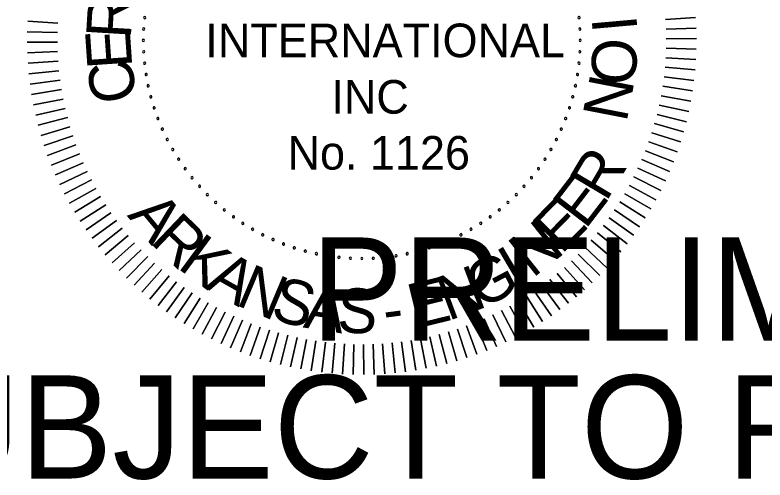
# Model space of a CAD drawing. Extents: x -0.54 to 1.64, y 0 to 0.92.
# Drawn here: x 1.1157 to 1.21, y 0.0548 to 0.1133 of the extents above; entities that cross this region are included whole.
import ezdxf

# ---------------------------------------------------------------- set-up
doc = ezdxf.new("R2010")
doc.units = 0
doc.layers.add('SHET_Stamp-Prelim', color=7, linetype='Continuous')
doc.layers.add('STAMP_COA', color=7, linetype='Continuous')

msp = doc.modelspace()

# ---------------------------------------------------------------- linework, layer by layer
at = {"layer": 'STAMP_COA'}
for points in [[(1.1211, 0.112275), (1.117313, 0.112493)], [(1.117313, 0.112493), (1.1211, 0.112275)], [(1.201265, 0.11296), (1.197481, 0.112701)], [(1.197481, 0.112701), (1.201265, 0.11296)], [(1.201335, 0.111641), (1.197545, 0.111501)], [(1.197545, 0.111501), (1.201335, 0.111641)], [(1.12105, 0.111074), (1.117258, 0.111172)], [(1.117258, 0.111172), (1.12105, 0.111074)], [(1.201363, 0.11032), (1.19757, 0.110299)], [(1.19757, 0.110299), (1.201363, 0.11032)], [(1.121038, 0.109872), (1.117245, 0.109851)], [(1.117245, 0.109851), (1.121038, 0.109872)], [(1.121064, 0.10867), (1.117273, 0.10853)], [(1.117273, 0.10853), (1.121064, 0.10867)], [(1.20135, 0.108999), (1.197558, 0.109097)], [(1.197558, 0.109097), (1.20135, 0.108999)], [(1.201295, 0.107679), (1.197508, 0.107896)], [(1.197508, 0.107896), (1.201295, 0.107679)], [(1.121127, 0.10747), (1.117343, 0.107211)], [(1.117343, 0.107211), (1.121127, 0.10747)], [(1.201199, 0.106361), (1.19742, 0.106697)], [(1.19742, 0.106697), (1.201199, 0.106361)], [(1.121228, 0.106272), (1.117454, 0.105894)], [(1.117454, 0.105894), (1.121228, 0.106272)], [(1.121366, 0.105078), (1.117606, 0.104582)], [(1.117606, 0.104582), (1.121366, 0.105078)], [(1.201061, 0.105047), (1.197295, 0.105501)], [(1.197295, 0.105501), (1.201061, 0.105047)], [(1.121542, 0.103889), (1.117799, 0.103275)], [(1.117799, 0.103275), (1.121542, 0.103889)], [(1.200882, 0.103738), (1.197132, 0.10431)], [(1.197132, 0.10431), (1.200882, 0.103738)], [(1.200662, 0.102435), (1.196932, 0.103125)], [(1.196932, 0.103125), (1.200662, 0.102435)], [(1.121756, 0.102706), (1.118034, 0.101974)], [(1.118034, 0.101974), (1.121756, 0.102706)], [(1.200401, 0.101139), (1.196695, 0.101946)], [(1.196695, 0.101946), (1.200401, 0.101139)], [(1.122006, 0.10153), (1.118309, 0.100682)], [(1.118309, 0.100682), (1.122006, 0.10153)], [(1.122293, 0.100363), (1.118625, 0.099399)], [(1.118625, 0.099399), (1.122293, 0.100363)], [(1.2001, 0.099853), (1.196421, 0.100776)], [(1.196421, 0.100776), (1.2001, 0.099853)], [(1.122617, 0.099205), (1.11898, 0.098126)], [(1.11898, 0.098126), (1.122617, 0.099205)], [(1.199759, 0.098577), (1.19611, 0.099614)], [(1.19611, 0.099614), (1.199759, 0.098577)], [(1.122977, 0.098058), (1.119376, 0.096866)], [(1.119376, 0.096866), (1.122977, 0.098058)], [(1.199377, 0.097312), (1.195763, 0.098464)], [(1.195763, 0.098464), (1.199377, 0.097312)], [(1.198956, 0.096059), (1.19538, 0.097324)], [(1.19538, 0.097324), (1.198956, 0.096059)], [(1.123372, 0.096923), (1.119811, 0.095618)], [(1.119811, 0.095618), (1.123372, 0.096923)], [(1.198496, 0.094821), (1.194961, 0.096197)], [(1.194961, 0.096197), (1.198496, 0.094821)], [(1.123804, 0.095801), (1.120285, 0.094385)], [(1.120285, 0.094385), (1.123804, 0.095801)], [(1.12427, 0.094693), (1.120797, 0.093167)], [(1.120797, 0.093167), (1.12427, 0.094693)], [(1.197997, 0.093597), (1.194508, 0.095084)], [(1.194508, 0.095084), (1.197997, 0.093597)], [(1.124771, 0.0936), (1.121348, 0.091966)], [(1.121348, 0.091966), (1.124771, 0.0936)], [(1.19746, 0.09239), (1.194019, 0.093986)], [(1.194019, 0.093986), (1.19746, 0.09239)], [(1.125306, 0.092523), (1.121936, 0.090782)], [(1.121936, 0.090782), (1.125306, 0.092523)], [(1.196885, 0.0912), (1.193496, 0.092903)], [(1.193496, 0.092903), (1.196885, 0.0912)], [(1.125874, 0.091464), (1.12256, 0.089618)], [(1.12256, 0.089618), (1.125874, 0.091464)], [(1.196274, 0.090029), (1.19294, 0.091838)], [(1.19294, 0.091838), (1.196274, 0.090029)], [(1.195625, 0.088877), (1.19235, 0.09079)], [(1.19235, 0.09079), (1.195625, 0.088877)], [(1.126475, 0.090423), (1.123221, 0.088474)], [(1.123221, 0.088474), (1.126475, 0.090423)], [(1.194941, 0.087747), (1.191727, 0.089762)], [(1.191727, 0.089762), (1.194941, 0.087747)], [(1.127109, 0.089402), (1.123918, 0.087351)], [(1.123918, 0.087351), (1.127109, 0.089402)], [(1.194222, 0.086639), (1.191073, 0.088753)], [(1.191073, 0.088753), (1.194222, 0.086639)], [(1.127775, 0.0884), (1.12465, 0.086251)], [(1.12465, 0.086251), (1.127775, 0.0884)], [(1.193468, 0.085553), (1.190387, 0.087766)], [(1.190387, 0.087766), (1.193468, 0.085553)], [(1.128471, 0.087421), (1.125415, 0.085174)], [(1.125415, 0.085174), (1.128471, 0.087421)], [(1.192681, 0.084492), (1.189671, 0.086801)], [(1.189671, 0.086801), (1.192681, 0.084492)], [(1.129199, 0.086464), (1.126214, 0.084122)], [(1.126214, 0.084122), (1.129199, 0.086464)], [(1.191861, 0.083457), (1.188925, 0.085858)], [(1.188925, 0.085858), (1.191861, 0.083457)], [(1.129955, 0.08553), (1.127046, 0.083095)], [(1.127046, 0.083095), (1.129955, 0.08553)], [(1.191008, 0.082447), (1.188149, 0.08494)], [(1.188149, 0.08494), (1.191008, 0.082447)], [(1.130741, 0.08462), (1.12791, 0.082096)], [(1.12791, 0.082096), (1.130741, 0.08462)], [(1.190124, 0.081465), (1.187345, 0.084046)], [(1.187345, 0.084046), (1.190124, 0.081465)], [(1.131555, 0.083735), (1.128805, 0.081123)], [(1.128805, 0.081123), (1.131555, 0.083735)], [(1.18921, 0.080511), (1.186513, 0.083178)], [(1.186513, 0.083178), (1.18921, 0.080511)], [(1.132397, 0.082877), (1.129729, 0.08018)], [(1.129729, 0.08018), (1.132397, 0.082877)], [(1.133265, 0.082045), (1.130683, 0.079265)], [(1.130683, 0.079265), (1.133265, 0.082045)], [(1.188266, 0.079586), (1.185654, 0.082337)], [(1.185654, 0.082337), (1.188266, 0.079586)], [(1.131666, 0.078382), (1.134158, 0.081241)], [(1.134158, 0.081241), (1.131666, 0.078382)], [(1.187294, 0.078692), (1.18477, 0.081523)], [(1.18477, 0.081523), (1.187294, 0.078692)], [(1.132675, 0.077529), (1.135077, 0.080465)], [(1.135077, 0.080465), (1.132675, 0.077529)], [(1.186294, 0.077828), (1.18386, 0.080737)], [(1.18386, 0.080737), (1.186294, 0.077828)], [(1.133711, 0.076709), (1.136019, 0.079719)], [(1.136019, 0.079719), (1.133711, 0.076709)], [(1.184215, 0.076197), (1.181969, 0.079253)], [(1.181969, 0.079253), (1.184215, 0.076197)], [(1.185268, 0.076996), (1.182926, 0.07998)], [(1.182926, 0.07998), (1.185268, 0.076996)], [(1.134772, 0.075921), (1.136984, 0.079002)], [(1.136984, 0.079002), (1.134772, 0.075921)], [(1.135857, 0.075168), (1.137972, 0.078317)], [(1.137972, 0.078317), (1.135857, 0.075168)], [(1.183139, 0.075431), (1.180989, 0.078556)], [(1.180989, 0.078556), (1.183139, 0.075431)], [(1.136966, 0.074448), (1.13898, 0.077662)], [(1.13898, 0.077662), (1.136966, 0.074448)], [(1.182038, 0.074699), (1.179988, 0.077891)], [(1.179988, 0.077891), (1.182038, 0.074699)], [(1.138096, 0.073764), (1.140009, 0.07704)], [(1.140009, 0.07704), (1.138096, 0.073764)], [(1.139247, 0.073116), (1.141056, 0.07645)], [(1.141056, 0.07645), (1.139247, 0.073116)], [(1.179772, 0.073342), (1.177926, 0.076655)], [(1.177926, 0.076655), (1.179772, 0.073342)], [(1.180916, 0.074003), (1.178967, 0.077257)], [(1.178967, 0.077257), (1.180916, 0.074003)], [(1.140418, 0.072504), (1.142122, 0.075893)], [(1.142122, 0.075893), (1.140418, 0.072504)], [(1.177424, 0.072129), (1.17579, 0.075552)], [(1.17579, 0.075552), (1.177424, 0.072129)], [(1.178607, 0.072717), (1.176866, 0.076087)], [(1.176866, 0.076087), (1.178607, 0.072717)], [(1.141608, 0.07193), (1.143204, 0.075371)], [(1.143204, 0.075371), (1.141608, 0.07193)], [(1.142815, 0.071393), (1.144302, 0.074882)], [(1.144302, 0.074882), (1.142815, 0.071393)], [(1.175005, 0.071066), (1.173589, 0.074585)], [(1.173589, 0.074585), (1.175005, 0.071066)], [(1.176223, 0.071579), (1.174697, 0.075051)], [(1.174697, 0.075051), (1.176223, 0.071579)], [(1.144039, 0.070894), (1.145416, 0.074428)], [(1.145416, 0.074428), (1.144039, 0.070894)], [(1.145278, 0.070434), (1.146543, 0.07401)], [(1.146543, 0.07401), (1.145278, 0.070434)], [(1.14653, 0.070013), (1.147682, 0.073626)], [(1.147682, 0.073626), (1.14653, 0.070013)], [(1.172524, 0.070157), (1.171332, 0.073758)], [(1.171332, 0.073758), (1.172524, 0.070157)], [(1.173772, 0.070592), (1.172467, 0.074154)], [(1.172467, 0.074154), (1.173772, 0.070592)], [(1.147795, 0.069631), (1.148833, 0.073279)], [(1.148833, 0.073279), (1.147795, 0.069631)], [(1.149071, 0.06929), (1.149994, 0.072969)], [(1.149994, 0.072969), (1.149071, 0.06929)], [(1.150358, 0.068988), (1.151165, 0.072695)], [(1.151165, 0.072695), (1.150358, 0.068988)], [(1.168708, 0.06909), (1.16786, 0.072788)], [(1.16786, 0.072788), (1.168708, 0.06909)], [(1.169991, 0.069406), (1.169027, 0.073075)], [(1.169027, 0.073075), (1.169991, 0.069406)], [(1.171263, 0.069762), (1.170185, 0.073398)], [(1.170185, 0.073398), (1.171263, 0.069762)], [(1.151653, 0.068728), (1.152343, 0.072457)], [(1.152343, 0.072457), (1.151653, 0.068728)], [(1.152956, 0.068508), (1.153529, 0.072257)], [(1.153529, 0.072257), (1.152956, 0.068508)], [(1.154265, 0.068329), (1.15472, 0.072094)], [(1.15472, 0.072094), (1.154265, 0.068329)], [(1.155579, 0.068191), (1.155915, 0.071969)], [(1.155915, 0.071969), (1.155579, 0.068191)], [(1.156897, 0.068095), (1.157114, 0.071882)], [(1.157114, 0.071882), (1.156897, 0.068095)], [(1.158217, 0.06804), (1.158315, 0.071832)], [(1.158315, 0.071832), (1.158217, 0.06804)], [(1.159538, 0.068026), (1.159517, 0.071819)], [(1.159517, 0.071819), (1.159538, 0.068026)], [(1.160859, 0.068055), (1.160719, 0.071845)], [(1.160719, 0.071845), (1.160859, 0.068055)], [(1.162179, 0.068124), (1.16192, 0.071908)], [(1.16192, 0.071908), (1.162179, 0.068124)], [(1.163496, 0.068235), (1.163118, 0.072009)], [(1.163118, 0.072009), (1.163496, 0.068235)], [(1.164808, 0.068387), (1.164312, 0.072148)], [(1.164312, 0.072148), (1.164808, 0.068387)], [(1.166115, 0.068581), (1.165501, 0.072324)], [(1.165501, 0.072324), (1.166115, 0.068581)], [(1.167415, 0.068815), (1.166684, 0.072537)], [(1.166684, 0.072537), (1.167415, 0.068815)]]:
    msp.add_lwpolyline(points, dxfattribs=at)
for centre, start, end in [((1.132005, 0.112955), 84, 264), ((1.132005, 0.112955), 264, 84), ((1.186603, 0.112955), 96, 276), ((1.186603, 0.112955), 276, 96), ((1.131892, 0.111522), 87, 267), ((1.131892, 0.111522), 267, 87), ((1.186716, 0.111522), 93, 273), ((1.186716, 0.111522), 273, 93), ((1.131854, 0.110086), 90, 270), ((1.131854, 0.110086), 270, 90), ((1.186754, 0.110086), 90, 270), ((1.186754, 0.110086), 270, 90), ((1.131892, 0.108649), 93, 273), ((1.131892, 0.108649), 273, 93), ((1.186716, 0.108649), 87, 267), ((1.186716, 0.108649), 267, 87), ((1.132005, 0.107216), 96, 276), ((1.132005, 0.107216), 276, 96), ((1.186603, 0.107216), 84, 264), ((1.186603, 0.107216), 264, 84), ((1.132192, 0.105791), 99, 279), ((1.132192, 0.105791), 279, 99), ((1.186416, 0.105791), 81, 261), ((1.186416, 0.105791), 261, 81), ((1.132454, 0.104378), 102, 282), ((1.132454, 0.104378), 282, 102), ((1.186154, 0.104378), 78, 258), ((1.186154, 0.104378), 258, 78), ((1.13279, 0.102981), 105, 285), ((1.13279, 0.102981), 285, 105), ((1.185818, 0.102981), 75, 255), ((1.185818, 0.102981), 255, 75), ((1.133198, 0.101603), 108, 288), ((1.133198, 0.101603), 288, 108), ((1.18541, 0.101603), 72, 252), ((1.18541, 0.101603), 252, 72), ((1.133678, 0.100248), 111, 291), ((1.133678, 0.100248), 291, 111), ((1.184931, 0.100248), 69, 249), ((1.184931, 0.100248), 249, 69), ((1.134227, 0.098921), 114, 294), ((1.134227, 0.098921), 294, 114), ((1.184381, 0.098921), 66, 246), ((1.184381, 0.098921), 246, 66), ((1.134846, 0.097624), 117, 297), ((1.134846, 0.097624), 297, 117), ((1.183762, 0.097624), 63, 243), ((1.183762, 0.097624), 243, 63), ((1.135532, 0.096361), 120, 300), ((1.135532, 0.096361), 300, 120), ((1.183076, 0.096361), 60, 240), ((1.183076, 0.096361), 240, 60), ((1.136283, 0.095135), 123, 303), ((1.136283, 0.095135), 303, 123), ((1.182325, 0.095135), 57, 237), ((1.182325, 0.095135), 237, 57), ((1.137097, 0.093951), 126, 306), ((1.137097, 0.093951), 306, 126), ((1.181511, 0.093951), 54, 234), ((1.181511, 0.093951), 234, 54), ((1.137972, 0.092811), 129, 309), ((1.137972, 0.092811), 309, 129), ((1.180636, 0.092811), 51, 231), ((1.180636, 0.092811), 231, 51), ((1.138905, 0.091718), 132, 312), ((1.138905, 0.091718), 312, 132), ((1.179703, 0.091718), 48, 228), ((1.179703, 0.091718), 228, 48), ((1.139894, 0.090676), 135, 315), ((1.139894, 0.090676), 315, 135), ((1.178714, 0.090676), 45, 225), ((1.178714, 0.090676), 225, 45), ((1.140937, 0.089686), 138, 318), ((1.140937, 0.089686), 318, 138), ((1.177671, 0.089686), 42, 222), ((1.177671, 0.089686), 222, 42), ((1.142029, 0.088753), 141, 321), ((1.142029, 0.088753), 321, 141), ((1.176579, 0.088753), 39, 219), ((1.176579, 0.088753), 219, 39), ((1.14317, 0.087878), 144, 324), ((1.14317, 0.087878), 324, 144), ((1.175439, 0.087878), 36, 216), ((1.175439, 0.087878), 216, 36), ((1.144354, 0.087064), 147, 327), ((1.144354, 0.087064), 327, 147), ((1.174254, 0.087064), 33, 213), ((1.174254, 0.087064), 213, 33), ((1.145579, 0.086313), 150, 330), ((1.145579, 0.086313), 330, 150), ((1.173029, 0.086313), 30, 210), ((1.173029, 0.086313), 210, 30), ((1.146842, 0.085628), 153, 333), ((1.146842, 0.085628), 333, 153), ((1.148139, 0.085009), 156, 336), ((1.148139, 0.085009), 336, 156), ((1.170469, 0.085009), 24, 204), ((1.170469, 0.085009), 204, 24), ((1.171766, 0.085628), 27, 207), ((1.171766, 0.085628), 207, 27), ((1.149467, 0.084459), 159, 339), ((1.149467, 0.084459), 339, 159), ((1.150822, 0.083979), 162, 342), ((1.150822, 0.083979), 342, 162), ((1.167786, 0.083979), 18, 198), ((1.167786, 0.083979), 198, 18), ((1.169141, 0.084459), 21, 201), ((1.169141, 0.084459), 201, 21), ((1.1522, 0.083571), 165, 345), ((1.1522, 0.083571), 345, 165), ((1.153597, 0.083236), 168, 348), ((1.153597, 0.083236), 348, 168), ((1.15501, 0.082974), 171, 351), ((1.15501, 0.082974), 351, 171), ((1.163598, 0.082974), 9, 189), ((1.163598, 0.082974), 189, 9), ((1.165011, 0.083236), 12, 192), ((1.165011, 0.083236), 192, 12), ((1.166409, 0.083571), 15, 195), ((1.166409, 0.083571), 195, 15), ((1.156435, 0.082786), 174, 354), ((1.156435, 0.082786), 354, 174), ((1.157867, 0.082673), 357, 177), ((1.157867, 0.082673), 177, 357), ((1.159304, 0.082636), 0, 180), ((1.159304, 0.082636), 180, 0), ((1.160741, 0.082673), 3, 183), ((1.160741, 0.082673), 183, 3), ((1.162173, 0.082786), 6, 186), ((1.162173, 0.082786), 186, 6)]:
    msp.add_arc(centre, 0.000141, start, end, dxfattribs=at)

# ---------------------------------------------------------------- texts
at = {"layer": 'SHET_Stamp-Prelim'}
for s, p in [('PRELIMINARY', (1.152902, 0.072283)), ('SUBJECT TO REVISIONS', (1.092196, 0.05494))]:
    msp.add_text(s, height=0.013, dxfattribs=at).set_placement(p)
at = {"layer": 'STAMP_COA'}
for s, rotation, p in [('R', 86.62678, (1.130255, 0.11021)), ('I', 275.12163, (1.188171, 0.112928)), ('E', 93.92026, (1.130463, 0.106691)), ('O', 267.07425, (1.188369, 0.110507)), ('C', 101.21373, (1.131183, 0.102773)), ('N', 259.02687, (1.188073, 0.106078)), ('R', 59.22624, (1.190016, 0.089657)), ('E', 52.47651, (1.187402, 0.086189)), ('A', 309.58591, (1.129742, 0.088027)), ('E', 45.72678, (1.184399, 0.083053)), ('R', 316.33564, (1.132539, 0.084705)), ('N', 38.41963, (1.180757, 0.08008)), ('K', 323.64278, (1.135985, 0.081507)), ('I', 30.54955, (1.178711, 0.078529)), ('G', 27.74038, (1.174257, 0.076164)), ('A', 330.39251, (1.139505, 0.078964)), ('N', 337.14224, (1.1433, 0.076853)), ('N', 20.43323, (1.170156, 0.074743)), ('S', 344.44939, (1.147657, 0.075087)), ('E', 13.6835, (1.16591, 0.073749)), ('A', 351.19912, (1.151851, 0.073961)), ('S', 357.94885, (1.156149, 0.073335)), ('-', 7.50775, (1.162295, 0.073322))]:
    msp.add_text(s, height=0.005634, rotation=rotation, dxfattribs=at).set_placement(p)
for s, height, p in [(' INTERNATIONAL', 0.00422539, (1.138065, 0.107975)), ('INC', 0.0042254, (1.155478, 0.10087)), (' No. 1126', 0.0042254, (1.148399, 0.093827))]:
    msp.add_text(s, height=height, dxfattribs=at).set_placement(p)

doc.saveas('drawing.dxf')
